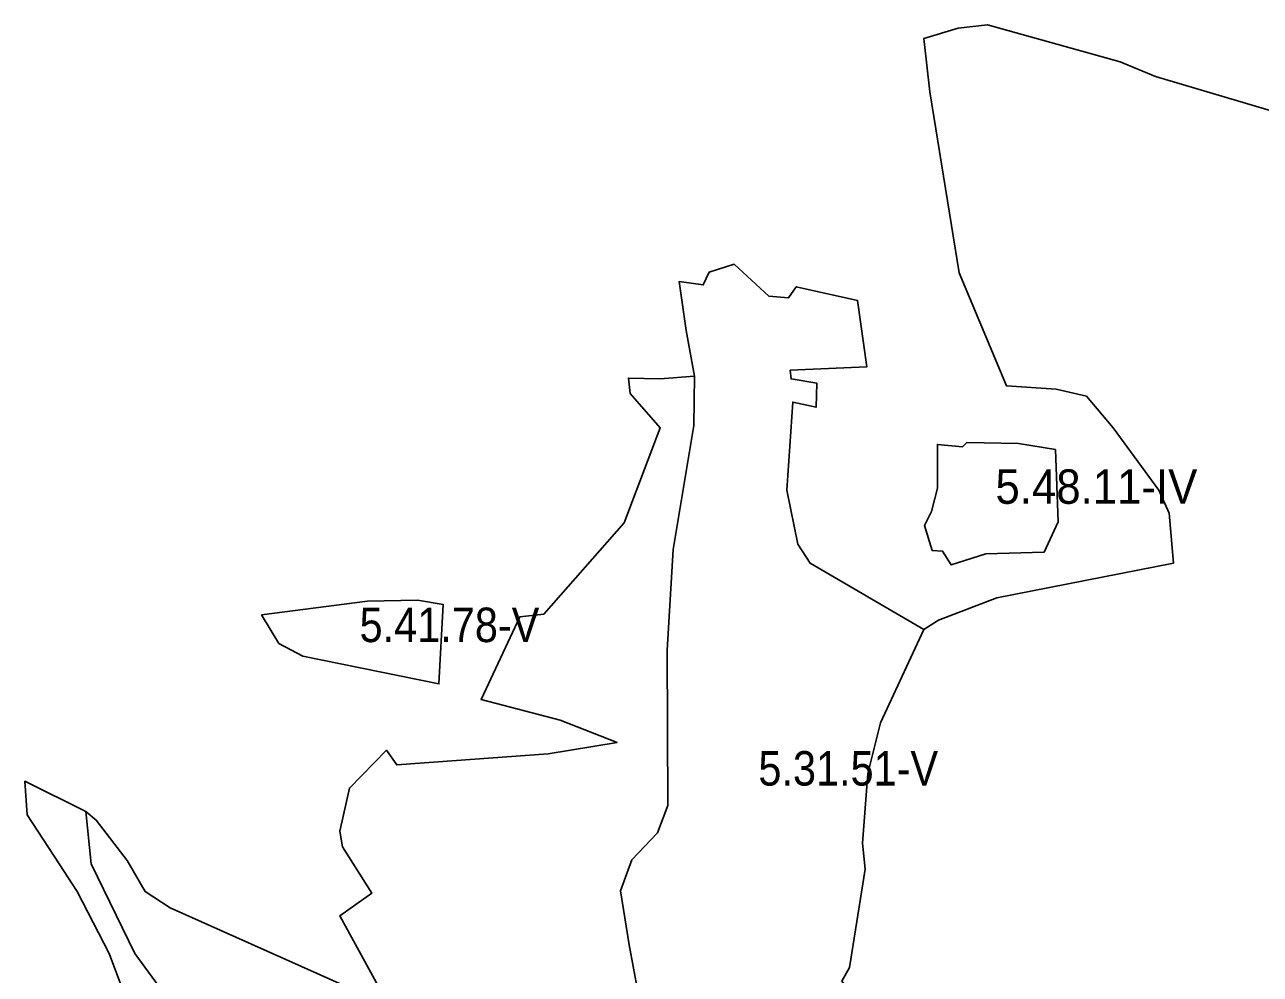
# Model space of a CAD drawing. Extents: x -591496 to -585489, y -1120610 to -1115685.
# Drawn here: x -589769 to -589052, y -1118638 to -1118087 of the extents above; entities that cross this region are included whole.
import ezdxf

# ---------------------------------------------------------------- set-up
doc = ezdxf.new("R2010")
doc.units = 0
doc.header["$LTSCALE"] = 8
doc.layers.add('40', color=7, linetype='Continuous', lineweight=25)
doc.layers.add('41', color=7, linetype='Continuous')

msp = doc.modelspace()

# ---------------------------------------------------------------- linework, layer by layer
at = {"layer": '40'}
for points in [[(-588991, -1118153), (-589112.5, -1118117), (-589133, -1118108.5), (-589210, -1118087), (-589227, -1118089), (-589247, -1118095), (-589243.5, -1118126), (-589226.5, -1118231), (-589199, -1118296.5), (-589170, -1118298.5), (-589152.5, -1118302.5), (-589137, -1118321), (-589110.5, -1118357), (-589104.5, -1118370.5), (-589102, -1118399.5), (-589204.5, -1118419.5), (-589238.5, -1118432.5), (-589247, -1118438), (-589313, -1118399.5), (-589320, -1118388.5), (-589326.5, -1118357), (-589323, -1118306), (-589309.5, -1118309), (-589309, -1118295), (-589324, -1118292.5), (-589324.5, -1118287.5), (-589280, -1118285.5), (-589285.5, -1118247), (-589321, -1118239), (-589325.5, -1118245.5), (-589337, -1118244.5), (-589357, -1118226), (-589371.5, -1118230.5), (-589375, -1118238), (-589389, -1118236), (-589385, -1118264.5), (-589380, -1118291), (-589400, -1118292.5), (-589418.5, -1118292), (-589417.5, -1118301), (-589400, -1118321), (-589421, -1118376), (-589467.5, -1118429), (-589481.5, -1118430.5), (-589504, -1118478.5), (-589458, -1118490.5), (-589425, -1118503.5)], [(-589290, -1118634), (-589281, -1118577), (-589282.5, -1118562), (-589279.5, -1118521.5), (-589272, -1118492), (-589247, -1118438), (-589238.5, -1118432.5), (-589204.5, -1118419.5), (-589102, -1118399.5), (-589104.5, -1118370.5), (-589110.5, -1118357), (-589137, -1118321), (-589152.5, -1118302.5), (-589170, -1118298.5), (-589199, -1118296.5), (-589226.5, -1118231), (-589243.5, -1118126), (-589247, -1118095), (-589227, -1118089), (-589210, -1118087), (-589133, -1118108.5), (-589112.5, -1118117), (-588991, -1118153)], [(-589413, -1118648), (-589418, -1118621), (-589423, -1118589.5), (-589416.5, -1118571.5), (-589401.5, -1118556), (-589395.5, -1118540), (-589396, -1118450), (-589392.5, -1118391.5), (-589380.5, -1118319.5), (-589380, -1118291), (-589385, -1118264.5), (-589389, -1118236), (-589375, -1118238), (-589371.5, -1118230.5), (-589357, -1118226), (-589337, -1118244.5), (-589325.5, -1118245.5), (-589321, -1118239), (-589285.5, -1118247), (-589280, -1118285.5), (-589324.5, -1118287.5), (-589324, -1118292.5), (-589309, -1118295), (-589309.5, -1118309), (-589323, -1118306), (-589326.5, -1118357), (-589320, -1118388.5), (-589313, -1118399.5), (-589247, -1118438), (-589272, -1118492), (-589279.5, -1118521.5), (-589282.5, -1118562), (-589281, -1118577), (-589290, -1118634), (-589294.5, -1118642)], [(-589563.5, -1118645), (-589586, -1118604), (-589567.5, -1118591), (-589584.5, -1118564), (-589586, -1118555), (-589580.5, -1118530), (-589559, -1118508), (-589553, -1118516.5), (-589465, -1118510), (-589425, -1118503.5), (-589458, -1118490.5), (-589504, -1118478.5), (-589481.5, -1118430.5), (-589467.5, -1118429), (-589421, -1118376), (-589400, -1118321), (-589417.5, -1118301), (-589418.5, -1118292), (-589400, -1118292.5), (-589380, -1118291), (-589380.5, -1118319.5), (-589392.5, -1118391.5), (-589396, -1118450), (-589395.5, -1118540), (-589401.5, -1118556), (-589416.5, -1118571.5), (-589423, -1118589.5), (-589418, -1118621), (-589413, -1118648)], [(-589425, -1118503.5), (-589465, -1118510), (-589553, -1118516.5), (-589559, -1118508), (-589580.5, -1118530), (-589586, -1118555), (-589584.5, -1118564), (-589567.5, -1118591), (-589586, -1118604), (-589563.5, -1118645)], [(-589561, -1118654.5), (-589684.5, -1118599.5), (-589699, -1118590), (-589709.5, -1118572), (-589727.5, -1118548.5), (-589733.5, -1118543.5), (-589769, -1118526), (-589767.5, -1118545.5), (-589749, -1118574), (-589738.5, -1118590), (-589720, -1118626), (-589706, -1118663)], [(-589706, -1118663), (-589720, -1118626), (-589738.5, -1118590), (-589749, -1118574), (-589767.5, -1118545.5), (-589769, -1118526), (-589733.5, -1118543.5), (-589730.5, -1118574), (-589705, -1118626), (-589669, -1118675)], [(-589669, -1118675), (-589705, -1118626), (-589730.5, -1118574), (-589733.5, -1118543.5), (-589727.5, -1118548.5), (-589709.5, -1118572), (-589699, -1118590), (-589684.5, -1118599.5), (-589561, -1118654.5)], [(-589046.5, -1118924.5), (-589061.5, -1118904.5), (-589089, -1118895.5), (-589100, -1118884.5), (-589111.5, -1118853), (-589126.5, -1118836.5), (-589174.5, -1118822), (-589210, -1118795), (-589222.5, -1118777.5), (-589247, -1118723.5), (-589273, -1118669.5), (-589294.5, -1118642), (-589290, -1118634)]]:
    msp.add_lwpolyline(points, dxfattribs=at)
for points in [[(-589222, -1118329.5), (-589224.5, -1118332), (-589239, -1118330.5), (-589239, -1118356), (-589242.5, -1118369.5), (-589246.5, -1118377.5), (-589242, -1118392), (-589236, -1118392.5), (-589231, -1118400.5), (-589211, -1118394), (-589177, -1118393), (-589169, -1118375.5), (-589170.5, -1118333.5), (-589192, -1118330)], [(-589192, -1118330), (-589170.5, -1118333.5), (-589169, -1118375.5), (-589177, -1118393), (-589211, -1118394), (-589231, -1118400.5), (-589236, -1118392.5), (-589242, -1118392), (-589246.5, -1118377.5), (-589242.5, -1118369.5), (-589239, -1118356), (-589239, -1118330.5), (-589224.5, -1118332), (-589222, -1118329.5)], [(-589607.5, -1118453.5), (-589528.5, -1118469.5), (-589526, -1118423.5), (-589541, -1118421), (-589570, -1118421.5), (-589631.5, -1118429.5), (-589621.5, -1118446)], [(-589526, -1118423.5), (-589528.5, -1118469.5), (-589607.5, -1118453.5), (-589621.5, -1118446), (-589631.5, -1118429.5), (-589570, -1118421.5), (-589541, -1118421)]]:
    msp.add_lwpolyline(points, close=True, dxfattribs=at)

# ---------------------------------------------------------------- texts
at = {"layer": '41'}
for s, width, p in [('5.48.11-IV', 0.95, (-589205.344, -1118365)), ('5.41.78-V', 0.9, (-589574.563, -1118445.25)), ('5.31.51-V', 0.9, (-589343, -1118528.5))]:
    msp.add_text(s, height=20, dxfattribs=dict(at, width=width)).set_placement(p)

doc.saveas('drawing.dxf')
